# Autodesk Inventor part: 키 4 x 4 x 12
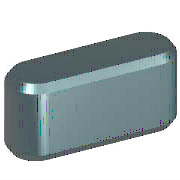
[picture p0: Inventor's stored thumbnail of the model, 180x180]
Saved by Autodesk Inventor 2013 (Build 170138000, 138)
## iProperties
IsCustomPart: 1
Created: 2012-02
Part Number: 키 4 x 4 x 12
Material: 강철, 연강
Description: 키 및 해당 키홈
Document SubType Name: Modeling
Standard: KS B 1311
Designer: mduedu
Standards Organization: KS
Language: ko-KR
Size Designation: 4 x 4 x 12
Categories: <MemberInstance><Categories><Category DisplayName="샤프트 부품" InternalName="7f7aeb1f-a693-4053-b835-cee3144e0d98" Mnemonic="SHFT"><Category DisplayName="키" Interna
Density: 7.86 g/cm^3
Mass: 1.38739 g
Surface Area: 1.94869 cm^2
Volume: 0.176513 cm^3
Author: mduedu
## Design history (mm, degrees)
workplane "Work Plane1"
workplane "Work Plane2"
sketch "스케치1"
  geometry: L1 (2, 2)-(10, 2); L2 (10, -2)-(2, -2); L3 (0, 9.4)-(0, -7.4) reference; L4 (-5, 0)-(30, 0) reference; L5 (12, 0)-(12, 7); A1 r 2 centre (2, 0) between (2, 2) and (2, -2); A2 r 2 centre (10, 0) between (10, -2) and (10, 2)
  constraints: 6 end point, 5 point on circle, 4 tangent, 3 point on line, 2 centre point, 1 horizontal, 1 parallel, 1 perpendicular
  dimensions: "d0" = 2 radius of A1 (= 0.5 x PB); "d13" = 2 radius of A2 (= 0.5 x PB); "d14" = 12 distance between parallel lines of L5 L3 (= NLG)
extrude "본체1" new body sketch "스케치1" taper "d3" = 0 deg; stored distance "d4" = 10
workplane "Work Plane3"
body "Solid1"
chamfer "모따기1" distance "d8" = 0.25 (= PHH); stored, may be unused: second distance "d9" = 0.25 (= PHH), angle "d15" = 45 deg
other parameters: "d1" = -2.5 (= -PNT), "d2" = 1.5 (= PH - PNT), "NLG" = 12 [user parameter; used in 3 equation terms], "PB" = 4 [user parameter; used in 2 equation terms], "PNT" = 2.5 [user parameter; used in 2 equation terms], "PH" = 4 [user parameter; used in 1 equation term], "PHH" = 0.25 [user parameter; used in 2 equation terms], "d10" = 0, "d16" = 0, "d17" = 0, "d18" = 0, "PLB2" = 12 (= NLG) [user parameter], "WDMAX" = 12 [user parameter], "PLB1" = 12 (= NLG) [user parameter], "RR" = 0.08 [user parameter], "PUEB" = 1.8 [user parameter]
